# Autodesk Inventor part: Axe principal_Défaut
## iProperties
Shininess: 64.0
Length Units: 11269
Angle Units: 11279
Time Units: 11290
Mass Units: 11283
Length Display Precision: 3
Angle Display Precision: 2
Compacted: True
Part Number: Axe principal_Défaut
Document SubType Name: Modeling
Created: 2006-01
Material: Par défaut
Designer: riri
Density: 0.0
Volumn: 0.0
Area: 0.0
PropertySet Name: Model Information
Control State: 0
Master: False
Checked Out: False
Author: riri
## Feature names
1. Base1
